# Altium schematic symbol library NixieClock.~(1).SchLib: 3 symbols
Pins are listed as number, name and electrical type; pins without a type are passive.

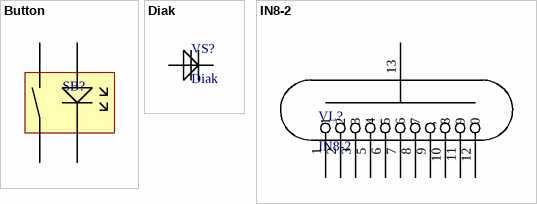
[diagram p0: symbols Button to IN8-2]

## Button
designator SB?  (value not drawn)
pins: 1, 2, 3, 4

## Diak
designator VS?
pins: 1, 2

## IN8-2
designator VL?
pins: 1, 2, 3, 5 4, 6 5, 7 6, 8 7, 9 ,, 10 8, 11 9, 12 0, 13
